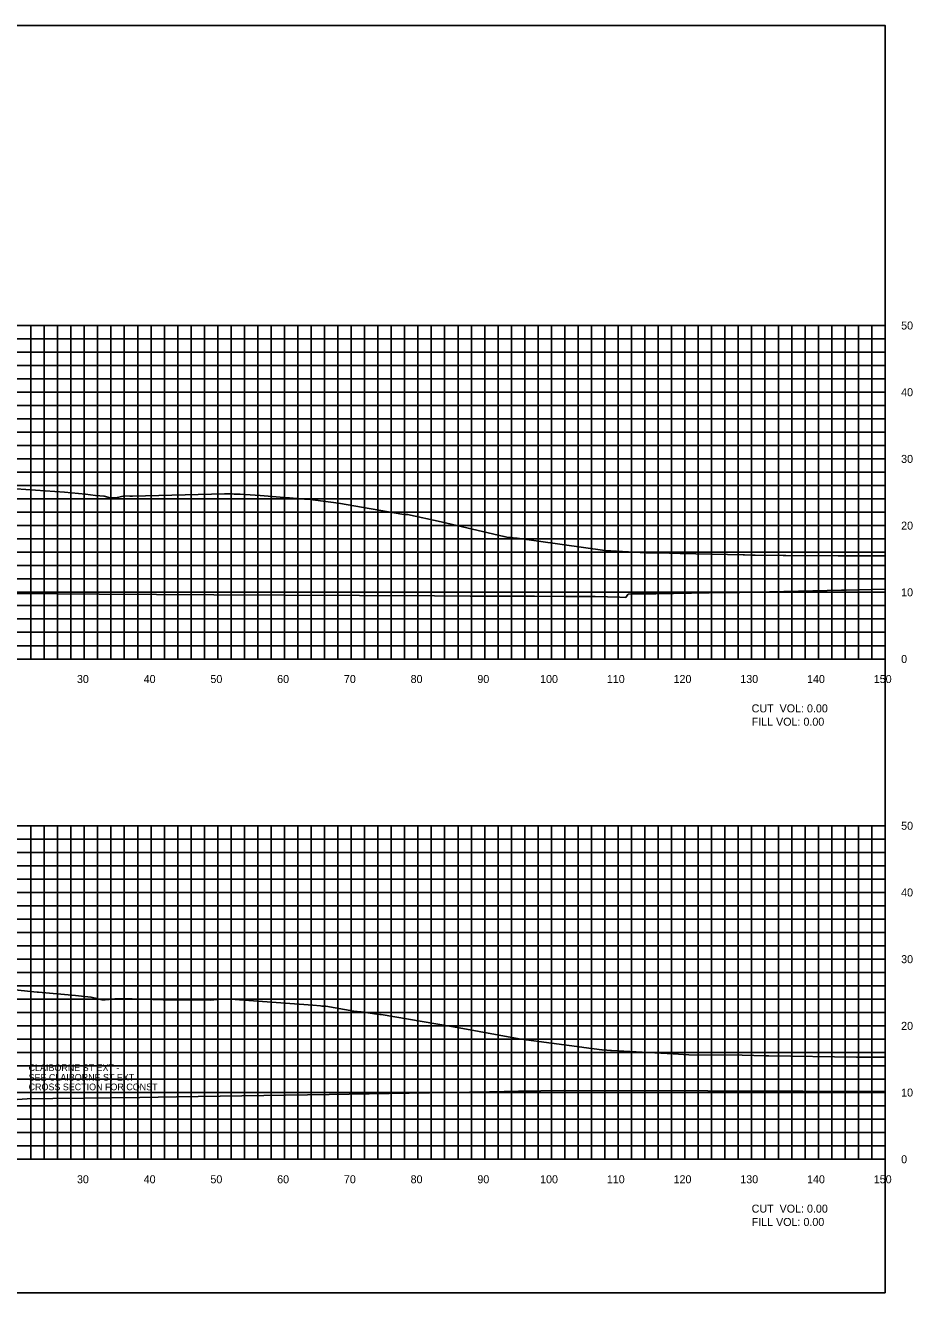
# Model space of a CAD drawing. Extents: x 1797305 to 1804485, y 245831 to 250849.
# Drawn here: x 1804352.2 to 1804485.1, y 250079.4 to 250269.4 of the extents above; entities that cross this region are included whole.
import ezdxf

# ---------------------------------------------------------------- set-up
doc = ezdxf.new("R2010")
doc.units = 0
for name, color, linetype in [('10', 7, 'Continuous'), ('29', 7, 'Continuous'), ('60', 7, 'Continuous'), ('CL-CNST', 7, 'Continuous'), ('EDPV-LINE', 7, 'Continuous'), ('Level 31', 7, 'Continuous'), ('LIMT-CSLINE', 7, 'Continuous'), ('M-ROADS', 7, 'Continuous')]:
    doc.layers.add(name, color=color, linetype=linetype)

msp = doc.modelspace()

# ---------------------------------------------------------------- linework, layer by layer
msp.add_lwpolyline([(1804181, 250079.43), (1804481, 250079.43), (1804481, 250269.43), (1804181, 250269.43)], close=True)
at = {"layer": '29'}
for p, q in [((1804181, 250224.43), (1804481, 250224.43)), ((1804353, 250174.43), (1804353, 250224.43)), ((1804355, 250174.43), (1804355, 250224.43)), ((1804357, 250174.43), (1804357, 250224.43)), ((1804359, 250174.43), (1804359, 250224.43)), ((1804361, 250174.43), (1804361, 250224.43)), ((1804363, 250174.43), (1804363, 250224.43)), ((1804365, 250174.43), (1804365, 250224.43)), ((1804367, 250174.43), (1804367, 250224.43)), ((1804369, 250174.43), (1804369, 250224.43)), ((1804371, 250174.43), (1804371, 250224.43)), ((1804373, 250174.43), (1804373, 250224.43)), ((1804375, 250174.43), (1804375, 250224.43)), ((1804377, 250174.43), (1804377, 250224.43)), ((1804379, 250174.43), (1804379, 250224.43)), ((1804381, 250174.43), (1804381, 250224.43)), ((1804383, 250174.43), (1804383, 250224.43)), ((1804385, 250174.43), (1804385, 250224.43)), ((1804387, 250174.43), (1804387, 250224.43)), ((1804389, 250174.43), (1804389, 250224.43)), ((1804391, 250174.43), (1804391, 250224.43)), ((1804393, 250174.43), (1804393, 250224.43)), ((1804395, 250174.43), (1804395, 250224.43)), ((1804397, 250174.43), (1804397, 250224.43)), ((1804399, 250174.43), (1804399, 250224.43)), ((1804401, 250174.43), (1804401, 250224.43)), ((1804403, 250174.43), (1804403, 250224.43)), ((1804405, 250174.43), (1804405, 250224.43)), ((1804407, 250174.43), (1804407, 250224.43)), ((1804409, 250174.43), (1804409, 250224.43)), ((1804411, 250174.43), (1804411, 250224.43)), ((1804413, 250174.43), (1804413, 250224.43)), ((1804415, 250174.43), (1804415, 250224.43)), ((1804417, 250174.43), (1804417, 250224.43)), ((1804419, 250174.43), (1804419, 250224.43)), ((1804421, 250174.43), (1804421, 250224.43)), ((1804423, 250174.43), (1804423, 250224.43)), ((1804425, 250174.43), (1804425, 250224.43)), ((1804427, 250174.43), (1804427, 250224.43)), ((1804429, 250174.43), (1804429, 250224.43)), ((1804431, 250174.43), (1804431, 250224.43)), ((1804433, 250174.43), (1804433, 250224.43)), ((1804435, 250174.43), (1804435, 250224.43)), ((1804437, 250174.43), (1804437, 250224.43)), ((1804439, 250174.43), (1804439, 250224.43)), ((1804441, 250174.43), (1804441, 250224.43)), ((1804443, 250174.43), (1804443, 250224.43)), ((1804445, 250174.43), (1804445, 250224.43)), ((1804447, 250174.43), (1804447, 250224.43)), ((1804449, 250174.43), (1804449, 250224.43)), ((1804451, 250174.43), (1804451, 250224.43)), ((1804453, 250174.43), (1804453, 250224.43)), ((1804455, 250174.43), (1804455, 250224.43)), ((1804457, 250174.43), (1804457, 250224.43)), ((1804459, 250174.43), (1804459, 250224.43)), ((1804461, 250174.43), (1804461, 250224.43)), ((1804463, 250174.43), (1804463, 250224.43)), ((1804465, 250174.43), (1804465, 250224.43)), ((1804467, 250174.43), (1804467, 250224.43)), ((1804469, 250174.43), (1804469, 250224.43)), ((1804471, 250174.43), (1804471, 250224.43)), ((1804473, 250174.43), (1804473, 250224.43)), ((1804475, 250174.43), (1804475, 250224.43)), ((1804477, 250174.43), (1804477, 250224.43)), ((1804479, 250174.43), (1804479, 250224.43)), ((1804481, 250174.43), (1804481, 250224.43)), ((1804181, 250222.43), (1804481, 250222.43)), ((1804181, 250220.43), (1804481, 250220.43)), ((1804181, 250218.43), (1804481, 250218.43)), ((1804181, 250216.43), (1804481, 250216.43)), ((1804181, 250214.43), (1804481, 250214.43)), ((1804181, 250212.43), (1804481, 250212.43)), ((1804181, 250210.43), (1804481, 250210.43)), ((1804181, 250208.43), (1804481, 250208.43)), ((1804181, 250206.43), (1804481, 250206.43)), ((1804181, 250204.43), (1804481, 250204.43)), ((1804181, 250202.43), (1804481, 250202.43)), ((1804181, 250200.43), (1804481, 250200.43)), ((1804181, 250198.43), (1804481, 250198.43)), ((1804181, 250196.43), (1804481, 250196.43)), ((1804181, 250194.43), (1804481, 250194.43)), ((1804181, 250192.43), (1804481, 250192.43)), ((1804181, 250190.43), (1804481, 250190.43)), ((1804181, 250188.43), (1804481, 250188.43)), ((1804181, 250186.43), (1804481, 250186.43)), ((1804181, 250184.43), (1804481, 250184.43)), ((1804181, 250182.43), (1804481, 250182.43)), ((1804181, 250180.43), (1804481, 250180.43)), ((1804181, 250178.43), (1804481, 250178.43)), ((1804181, 250176.43), (1804481, 250176.43)), ((1804181, 250174.43), (1804481, 250174.43)), ((1804181, 250149.43), (1804481, 250149.43)), ((1804353, 250099.43), (1804353, 250149.43)), ((1804355, 250099.43), (1804355, 250149.43)), ((1804357, 250099.43), (1804357, 250149.43)), ((1804359, 250099.43), (1804359, 250149.43)), ((1804361, 250099.43), (1804361, 250149.43)), ((1804363, 250099.43), (1804363, 250149.43)), ((1804365, 250099.43), (1804365, 250149.43)), ((1804367, 250099.43), (1804367, 250149.43)), ((1804369, 250099.43), (1804369, 250149.43)), ((1804371, 250099.43), (1804371, 250149.43)), ((1804373, 250099.43), (1804373, 250149.43)), ((1804375, 250099.43), (1804375, 250149.43)), ((1804377, 250099.43), (1804377, 250149.43)), ((1804379, 250099.43), (1804379, 250149.43)), ((1804381, 250099.43), (1804381, 250149.43)), ((1804383, 250099.43), (1804383, 250149.43)), ((1804385, 250099.43), (1804385, 250149.43)), ((1804387, 250099.43), (1804387, 250149.43)), ((1804389, 250099.43), (1804389, 250149.43)), ((1804391, 250099.43), (1804391, 250149.43)), ((1804393, 250099.43), (1804393, 250149.43)), ((1804395, 250099.43), (1804395, 250149.43)), ((1804397, 250099.43), (1804397, 250149.43)), ((1804399, 250099.43), (1804399, 250149.43)), ((1804401, 250099.43), (1804401, 250149.43)), ((1804403, 250099.43), (1804403, 250149.43)), ((1804405, 250099.43), (1804405, 250149.43)), ((1804407, 250099.43), (1804407, 250149.43)), ((1804409, 250099.43), (1804409, 250149.43)), ((1804411, 250099.43), (1804411, 250149.43)), ((1804413, 250099.43), (1804413, 250149.43)), ((1804415, 250099.43), (1804415, 250149.43)), ((1804417, 250099.43), (1804417, 250149.43)), ((1804419, 250099.43), (1804419, 250149.43)), ((1804421, 250099.43), (1804421, 250149.43)), ((1804423, 250099.43), (1804423, 250149.43)), ((1804425, 250099.43), (1804425, 250149.43)), ((1804427, 250099.43), (1804427, 250149.43)), ((1804429, 250099.43), (1804429, 250149.43)), ((1804431, 250099.43), (1804431, 250149.43)), ((1804433, 250099.43), (1804433, 250149.43)), ((1804435, 250099.43), (1804435, 250149.43)), ((1804437, 250099.43), (1804437, 250149.43)), ((1804439, 250099.43), (1804439, 250149.43)), ((1804441, 250099.43), (1804441, 250149.43)), ((1804443, 250099.43), (1804443, 250149.43)), ((1804445, 250099.43), (1804445, 250149.43)), ((1804447, 250099.43), (1804447, 250149.43)), ((1804449, 250099.43), (1804449, 250149.43)), ((1804451, 250099.43), (1804451, 250149.43)), ((1804453, 250099.43), (1804453, 250149.43)), ((1804455, 250099.43), (1804455, 250149.43)), ((1804457, 250099.43), (1804457, 250149.43)), ((1804459, 250099.43), (1804459, 250149.43)), ((1804461, 250099.43), (1804461, 250149.43)), ((1804463, 250099.43), (1804463, 250149.43)), ((1804465, 250099.43), (1804465, 250149.43)), ((1804467, 250099.43), (1804467, 250149.43)), ((1804469, 250099.43), (1804469, 250149.43)), ((1804471, 250099.43), (1804471, 250149.43)), ((1804473, 250099.43), (1804473, 250149.43)), ((1804475, 250099.43), (1804475, 250149.43)), ((1804477, 250099.43), (1804477, 250149.43)), ((1804479, 250099.43), (1804479, 250149.43)), ((1804481, 250099.43), (1804481, 250149.43)), ((1804181, 250147.43), (1804481, 250147.43)), ((1804181, 250145.43), (1804481, 250145.43)), ((1804181, 250143.43), (1804481, 250143.43)), ((1804181, 250141.43), (1804481, 250141.43)), ((1804181, 250139.43), (1804481, 250139.43)), ((1804181, 250137.43), (1804481, 250137.43)), ((1804181, 250135.43), (1804481, 250135.43)), ((1804181, 250133.43), (1804481, 250133.43)), ((1804181, 250131.43), (1804481, 250131.43)), ((1804181, 250129.43), (1804481, 250129.43)), ((1804181, 250127.43), (1804481, 250127.43)), ((1804181, 250125.43), (1804481, 250125.43)), ((1804181, 250123.43), (1804481, 250123.43)), ((1804181, 250121.43), (1804481, 250121.43)), ((1804181, 250119.43), (1804481, 250119.43)), ((1804181, 250117.43), (1804481, 250117.43)), ((1804181, 250115.43), (1804481, 250115.43)), ((1804181, 250113.43), (1804481, 250113.43)), ((1804181, 250111.43), (1804481, 250111.43)), ((1804181, 250109.43), (1804481, 250109.43)), ((1804181, 250107.43), (1804481, 250107.43)), ((1804181, 250105.43), (1804481, 250105.43)), ((1804181, 250103.43), (1804481, 250103.43)), ((1804181, 250101.43), (1804481, 250101.43)), ((1804181, 250099.43), (1804481, 250099.43))]:
    msp.add_line(p, q, dxfattribs=at)
at = {"layer": 'CL-CNST'}
for points in [[(1804350.87, 250184.24), (1804363.21, 250184.15), (1804380.43, 250184.05), (1804391.02, 250183.98), (1804413.47, 250183.88), (1804418.84, 250183.86), (1804428.44, 250183.83), (1804432.94, 250183.82), (1804437.56, 250183.8), (1804441.24, 250183.7), (1804442.13, 250183.67), (1804442.45, 250184.1), (1804442.51, 250184.17), (1804443.16, 250184.18), (1804443.26, 250184.18), (1804443.26, 250184.18), (1804443.27, 250184.18), (1804446.65, 250184.22), (1804454.65, 250184.33), (1804459.24, 250184.4), (1804460.39, 250184.43), (1804461.52, 250184.46), (1804474.47, 250184.74), (1804475.15, 250184.75), (1804481, 250184.88)], [(1804350.94, 250108.41), (1804352.42, 250108.47), (1804356.3, 250108.53), (1804360.88, 250108.59), (1804369.32, 250108.71), (1804374.83, 250108.8), (1804397.7, 250109.15), (1804421.7, 250109.55), (1804426.07, 250109.63), (1804432.78, 250109.75), (1804454.44, 250109.68), (1804468.66, 250109.63), (1804481, 250109.59)]]:
    msp.add_lwpolyline(points, dxfattribs=at)
at = {"layer": 'Level 31'}
for p, q in [((1804481, 250174.43), (1804481, 250224.43)), ((1804481.06, 250224.43), (1804481, 250224.43)), ((1804481.06, 250214.43), (1804481, 250214.43)), ((1804481.06, 250204.43), (1804481, 250204.43)), ((1804481.06, 250194.43), (1804481, 250194.43)), ((1804481.06, 250184.43), (1804481, 250184.43)), ((1804181, 250174.43), (1804481, 250174.43)), ((1804361, 250174.37), (1804361, 250174.43)), ((1804371, 250174.37), (1804371, 250174.43)), ((1804381, 250174.37), (1804381, 250174.43)), ((1804391, 250174.37), (1804391, 250174.43)), ((1804401, 250174.37), (1804401, 250174.43)), ((1804411, 250174.37), (1804411, 250174.43)), ((1804421, 250174.37), (1804421, 250174.43)), ((1804431, 250174.37), (1804431, 250174.43)), ((1804441, 250174.37), (1804441, 250174.43)), ((1804451, 250174.37), (1804451, 250174.43)), ((1804461, 250174.37), (1804461, 250174.43)), ((1804471, 250174.37), (1804471, 250174.43)), ((1804481, 250174.37), (1804481, 250174.43)), ((1804481.06, 250174.43), (1804481, 250174.43)), ((1804481, 250099.43), (1804481, 250149.43)), ((1804481.06, 250149.43), (1804481, 250149.43)), ((1804481.06, 250139.43), (1804481, 250139.43)), ((1804481.06, 250129.43), (1804481, 250129.43)), ((1804481.06, 250119.43), (1804481, 250119.43)), ((1804481.06, 250109.43), (1804481, 250109.43)), ((1804181, 250099.43), (1804481, 250099.43)), ((1804361, 250099.37), (1804361, 250099.43)), ((1804371, 250099.37), (1804371, 250099.43)), ((1804381, 250099.37), (1804381, 250099.43)), ((1804391, 250099.37), (1804391, 250099.43)), ((1804401, 250099.37), (1804401, 250099.43)), ((1804411, 250099.37), (1804411, 250099.43)), ((1804421, 250099.37), (1804421, 250099.43)), ((1804431, 250099.37), (1804431, 250099.43)), ((1804441, 250099.37), (1804441, 250099.43)), ((1804451, 250099.37), (1804451, 250099.43)), ((1804461, 250099.37), (1804461, 250099.43)), ((1804471, 250099.37), (1804471, 250099.43)), ((1804481, 250099.37), (1804481, 250099.43)), ((1804481.06, 250099.43), (1804481, 250099.43))]:
    msp.add_line(p, q, dxfattribs=at)
at = {"layer": 'M-ROADS'}
for points in [[(1804350.81, 250199.94), (1804358.01, 250199.43), (1804361.2, 250199.15), (1804362.66, 250198.94), (1804363.96, 250198.86), (1804364.9, 250198.59), (1804365.22, 250198.59), (1804365.66, 250198.59), (1804365.74, 250198.59), (1804367.03, 250198.88), (1804367.82, 250198.86), (1804367.87, 250198.86), (1804367.92, 250198.85), (1804367.98, 250198.85), (1804368.05, 250198.85), (1804368.12, 250198.85), (1804368.2, 250198.85), (1804368.23, 250198.85), (1804381.99, 250199.18), (1804382.47, 250199.19), (1804382.48, 250199.19), (1804382.84, 250199.18), (1804383.16, 250199.17), (1804383.45, 250199.16), (1804383.71, 250199.15), (1804383.94, 250199.14), (1804384.15, 250199.13), (1804384.34, 250199.12), (1804387.33, 250198.94), (1804390.94, 250198.66), (1804391.01, 250198.66), (1804391.74, 250198.58), (1804394, 250198.39), (1804394.2, 250198.39), (1804394.52, 250198.39), (1804399.11, 250197.78), (1804408.9, 250196.12), (1804409.13, 250196.12), (1804409.44, 250196.11), (1804414.46, 250194.99), (1804423.88, 250192.79), (1804423.93, 250192.79), (1804424.51, 250192.63), (1804424.96, 250192.63), (1804425, 250192.63), (1804425.58, 250192.56), (1804425.87, 250192.53), (1804438.98, 250190.68), (1804445.21, 250190.37), (1804448.7, 250190.28), (1804450.28, 250190.25), (1804459.72, 250190.04), (1804459.93, 250190.03), (1804461.04, 250190.02), (1804461.17, 250190.02), (1804461.54, 250190.02), (1804465.71, 250189.96), (1804466.13, 250189.95), (1804473.95, 250189.91), (1804474.31, 250189.91), (1804479.73, 250189.91), (1804481, 250189.91)], [(1804346.77, 250125.24), (1804353.94, 250124.46), (1804354.13, 250124.47), (1804359.66, 250123.96), (1804361.97, 250123.73), (1804362.02, 250123.73), (1804362.65, 250123.6), (1804363.44, 250123.37), (1804363.51, 250123.37), (1804363.67, 250123.34), (1804364.12, 250123.34), (1804365.36, 250123.44), (1804365.59, 250123.49), (1804365.77, 250123.49), (1804365.79, 250123.49), (1804365.8, 250123.49), (1804365.81, 250123.49), (1804365.82, 250123.49), (1804365.84, 250123.49), (1804365.86, 250123.49), (1804365.88, 250123.49), (1804365.9, 250123.49), (1804365.92, 250123.49), (1804365.95, 250123.49), (1804365.98, 250123.49), (1804366.01, 250123.49), (1804366.05, 250123.49), (1804366.09, 250123.49), (1804366.15, 250123.49), (1804366.21, 250123.49), (1804366.29, 250123.49), (1804366.38, 250123.49), (1804366.51, 250123.49), (1804366.67, 250123.49), (1804366.9, 250123.49), (1804366.97, 250123.49), (1804368.16, 250123.46), (1804371.27, 250123.38), (1804372.8, 250123.34), (1804379.94, 250123.3), (1804380.93, 250123.36), (1804381.11, 250123.36), (1804382.64, 250123.45), (1804382.89, 250123.44), (1804395.23, 250122.51), (1804396.4, 250122.42), (1804396.58, 250122.4), (1804396.98, 250122.4), (1804397.1, 250122.4), (1804397.11, 250122.4), (1804397.18, 250122.39), (1804401.4, 250121.63), (1804402.46, 250121.55), (1804402.5, 250121.55), (1804404.86, 250121.17), (1804405.31, 250121.11), (1804405.49, 250121.11), (1804415.71, 250119.4), (1804417.17, 250119.13), (1804426.15, 250117.5), (1804426.36, 250117.44), (1804426.48, 250117.44), (1804435.53, 250116.26), (1804435.85, 250116.21), (1804438.57, 250115.86), (1804438.61, 250115.86), (1804439.29, 250115.77), (1804439.84, 250115.74), (1804440, 250115.73), (1804449.22, 250115.23), (1804451.57, 250115.11), (1804459.56, 250115.03), (1804463.08, 250114.95), (1804463.36, 250114.95), (1804463.59, 250114.95), (1804476.71, 250114.74), (1804477.61, 250114.73), (1804477.62, 250114.73), (1804477.67, 250114.73), (1804478.11, 250114.73), (1804478.12, 250114.73), (1804478.24, 250114.73), (1804478.25, 250114.73), (1804479.63, 250114.72), (1804481, 250114.72)]]:
    msp.add_lwpolyline(points, dxfattribs=at)

# ---------------------------------------------------------------- texts
at = {"layer": '10'}
for s, p in [('30', (1804359.9, 250170.83)), ('40', (1804369.9, 250170.83)), ('50', (1804379.9, 250170.83)), ('60', (1804389.9, 250170.83)), ('70', (1804399.9, 250170.83)), ('80', (1804409.9, 250170.83)), ('90', (1804419.9, 250170.83)), ('100', (1804429.3, 250170.83)), ('110', (1804439.3, 250170.83)), ('120', (1804449.3, 250170.83)), ('130', (1804459.3, 250170.83)), ('140', (1804469.3, 250170.83)), ('150', (1804479.3, 250170.83)), ('30', (1804359.9, 250095.83)), ('40', (1804369.9, 250095.83)), ('50', (1804379.9, 250095.83)), ('60', (1804389.9, 250095.83)), ('70', (1804399.9, 250095.83)), ('80', (1804409.9, 250095.83)), ('90', (1804419.9, 250095.83)), ('100', (1804429.3, 250095.83)), ('110', (1804439.3, 250095.83)), ('120', (1804449.3, 250095.83)), ('130', (1804459.3, 250095.83)), ('140', (1804469.3, 250095.83)), ('150', (1804479.3, 250095.83))]:
    msp.add_text(s, height=1.2, dxfattribs=at).set_placement(p)
at = {"layer": '60'}
for s, p in [('50', (1804483.4, 250223.83)), ('40', (1804483.4, 250213.83)), ('30', (1804483.4, 250203.83)), ('20', (1804483.4, 250193.83)), ('10', (1804483.4, 250183.83)), ('0', (1804483.4, 250173.83)), ('50', (1804483.4, 250148.83)), ('40', (1804483.4, 250138.83)), ('30', (1804483.4, 250128.83)), ('20', (1804483.4, 250118.83)), ('10', (1804483.4, 250108.83)), ('0', (1804483.4, 250098.83))]:
    msp.add_text(s, height=1.2, dxfattribs=at).set_placement(p)
at = {"layer": 'EDPV-LINE'}
for s, p in [('CUT  VOL: 0.00', (1804461, 250166.43)), ('FILL VOL: 0.00', (1804461, 250164.43)), ('CUT  VOL: 0.00', (1804461, 250091.43)), ('FILL VOL: 0.00', (1804461, 250089.43))]:
    msp.add_text(s, height=1.2, dxfattribs=at).set_placement(p)
at = {"layer": 'LIMT-CSLINE'}
for s, p in [('CLAIBORNE ST EXT -', (1804352.66, 250112.66)), ('SEE CLAIBORNE ST EXT', (1804352.66, 250111.22)), ('CROSS SECTION FOR CONST ', (1804352.66, 250109.78))]:
    msp.add_text(s, height=1, dxfattribs=at).set_placement(p)

doc.saveas('drawing.dxf')
